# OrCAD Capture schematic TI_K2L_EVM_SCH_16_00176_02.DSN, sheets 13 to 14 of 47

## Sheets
13 PAGE36 : K2L_CLK_GEN2: size C; title: CDCM62008 Clk2, 100 / 156.25, Power Filter for Clock
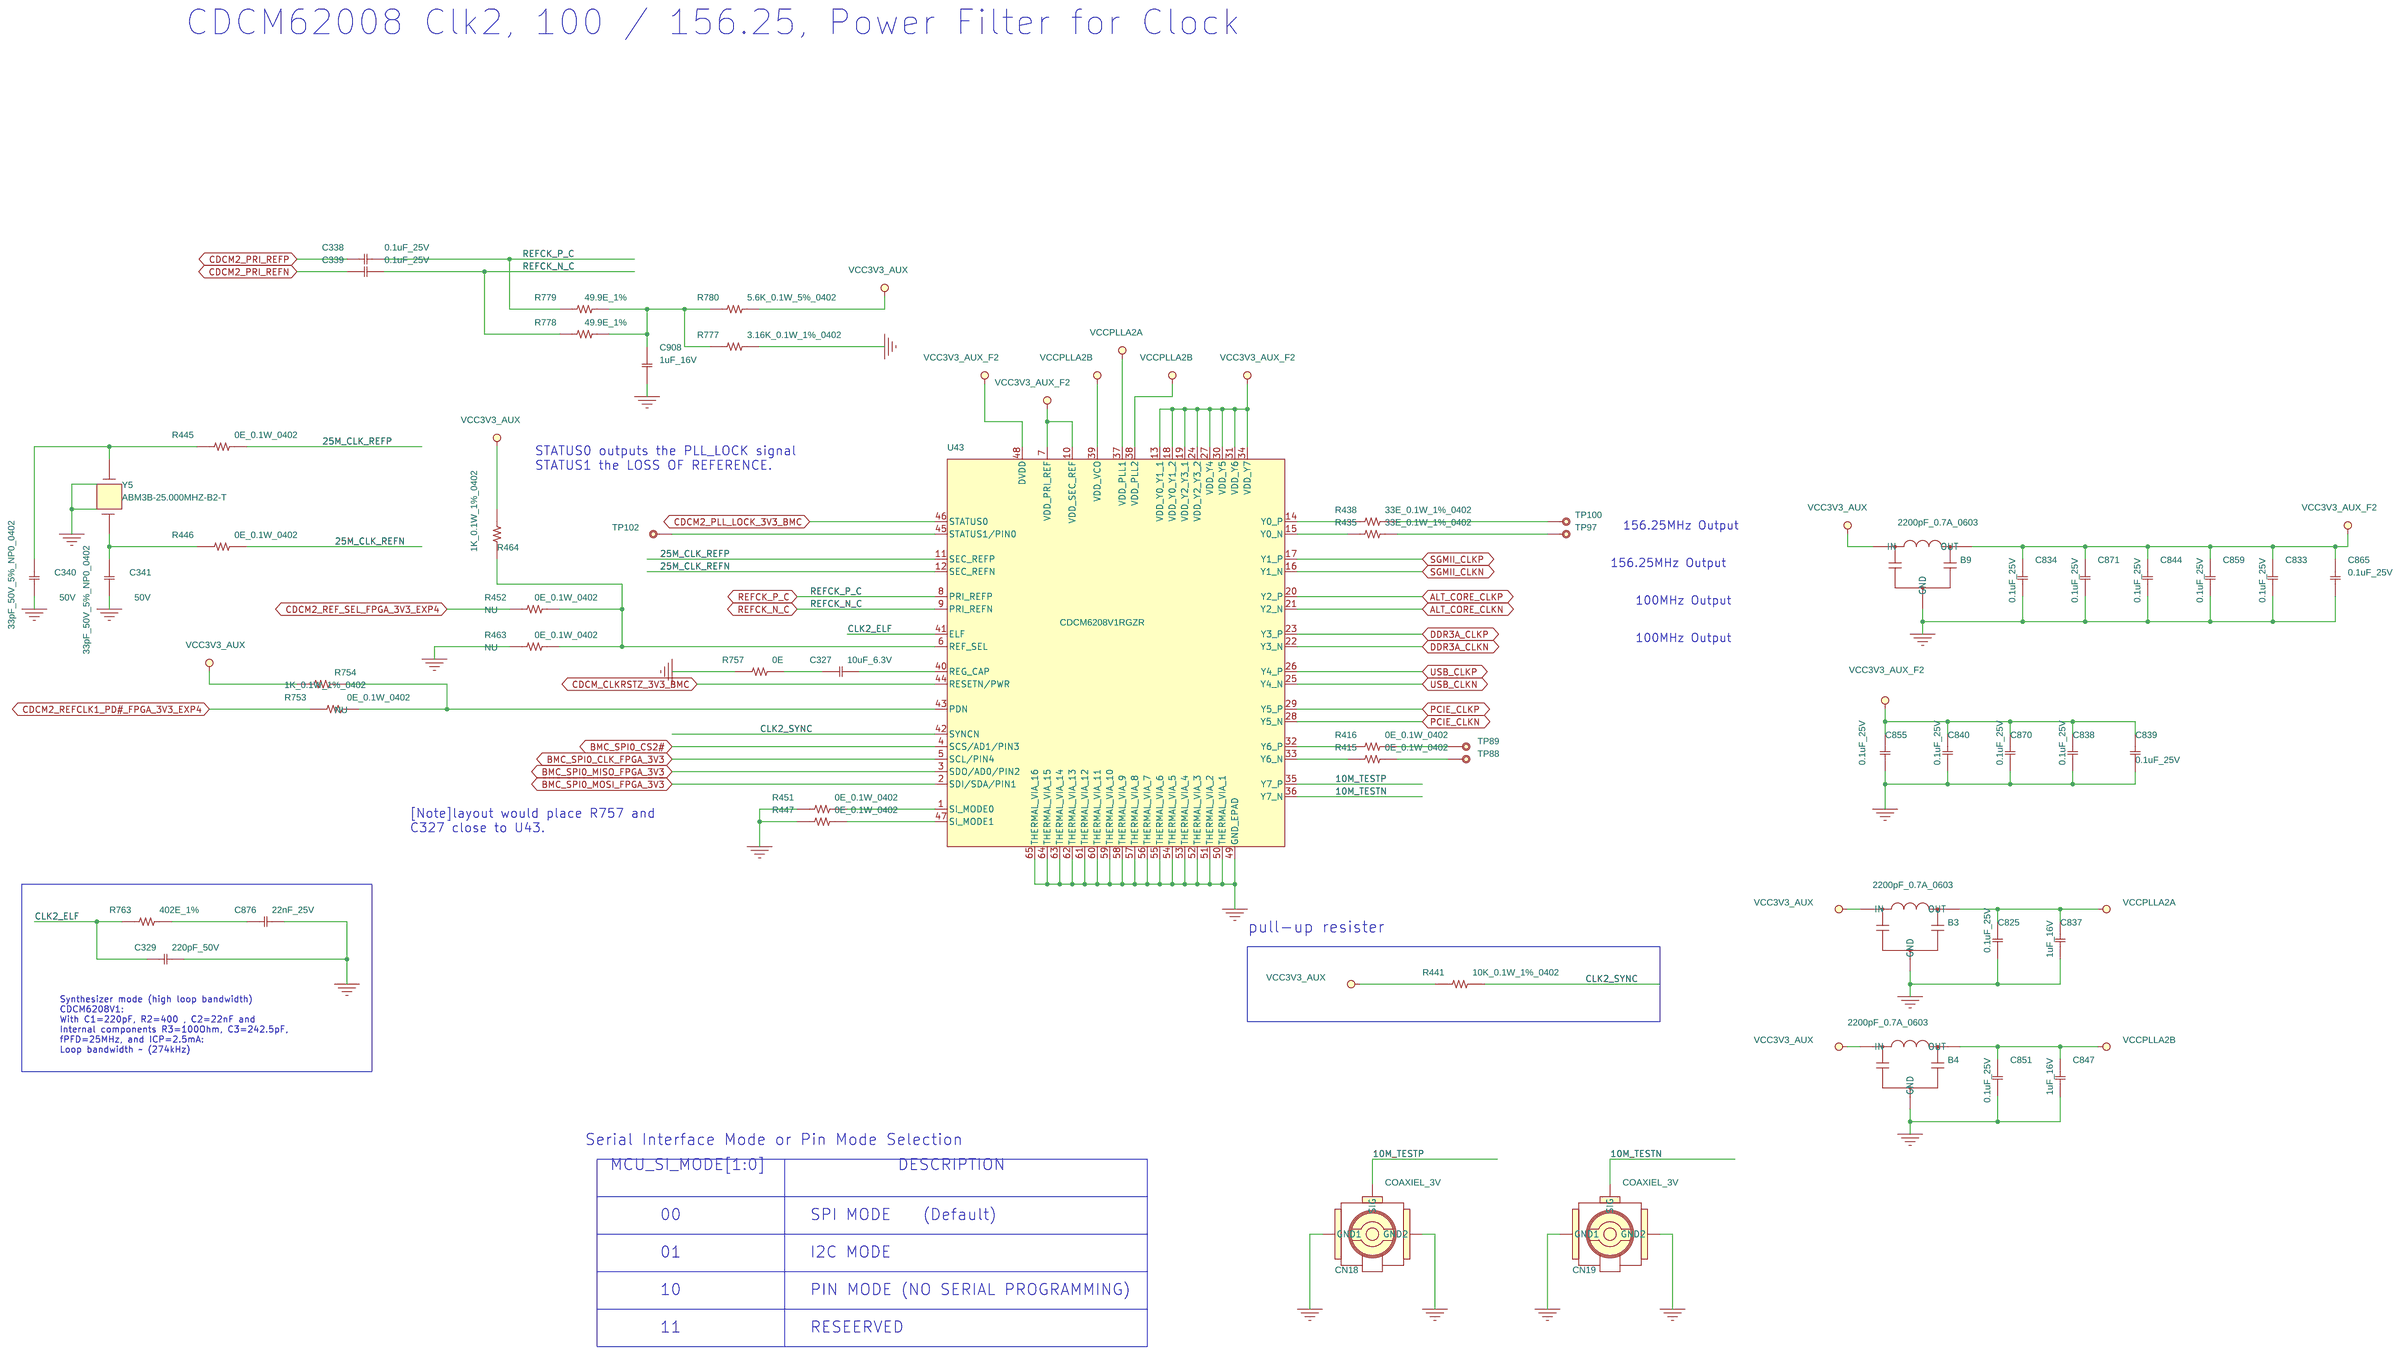
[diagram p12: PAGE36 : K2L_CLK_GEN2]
14 PAGE39 : K2L_XDS200_3: size C; title: XDS200 / debug hdr, oscillators
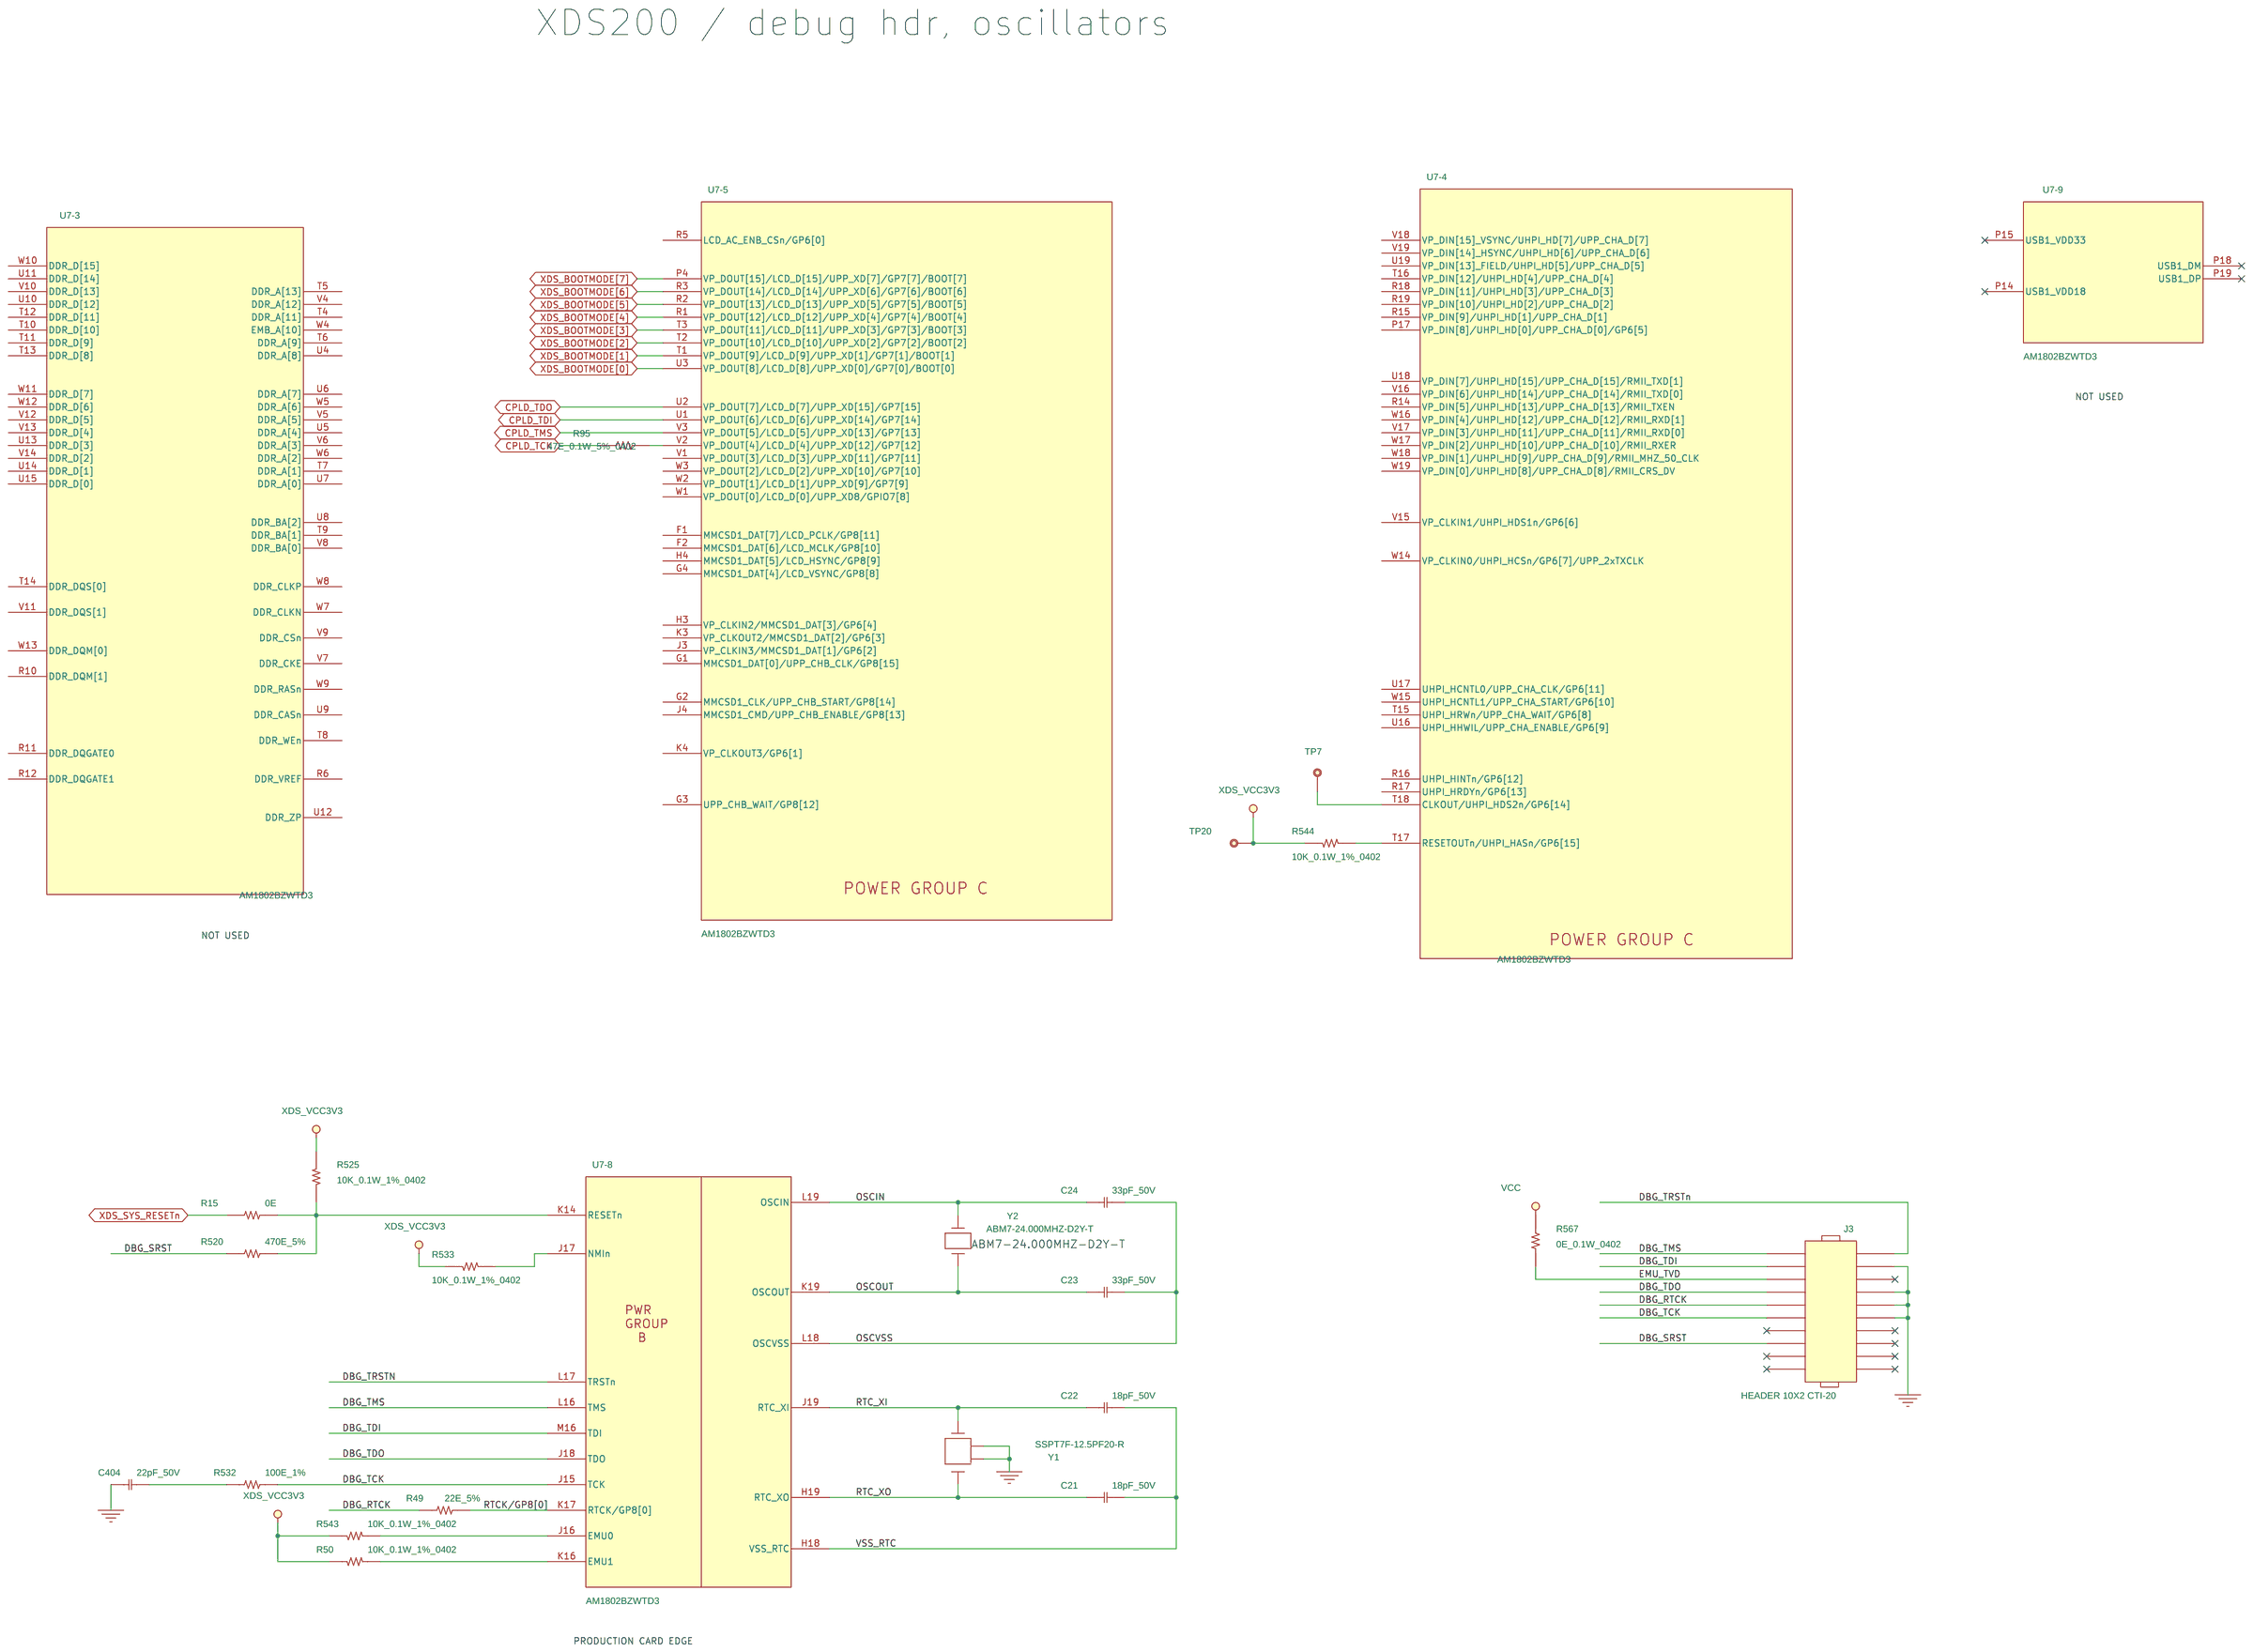
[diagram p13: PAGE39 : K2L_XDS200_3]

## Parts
sheet PAGE36 : K2L_CLK_GEN2
B3  2200pF_0.7A_0603  [L_3P_70_63X35]
B4  2200pF_0.7A_0603  [L_3P_70_63X35]
B9  2200pF_0.7A_0603  [L_3P_70_63X35]
C327  10uF_6.3V  [C0603]
C329  220pF_50V  [C0603]
C338  0.1uF_25V  [C0402]
C339  0.1uF_25V  [C0402]
C340  33pF_50V_5%_NP0_0402  [C0402]
C341  33pF_50V_5%_NP0_0402  [C0402]
C825  0.1uF_25V  [C0402]
C833  0.1uF_25V  [C0402]
C834  0.1uF_25V  [C0402]
C837  1uF_16V  [C0402]
C838  0.1uF_25V  [C0402]
C839  0.1uF_25V  [C0402]
C840  0.1uF_25V  [C0402]
C844  0.1uF_25V  [C0402]
C847  1uF_16V  [C0402]
C851  0.1uF_25V  [C0402]
C855  0.1uF_25V  [C0402]
C859  0.1uF_25V  [C0402]
C865  0.1uF_25V  [C0402]
C870  0.1uF_25V  [C0402]
C871  0.1uF_25V  [C0402]
C876  22nF_25V  [C0402]
C908  1uF_16V  [C0402]
CN18  COAXIEL_3V  [HS_UFL-R-SMT-1]
CN19  COAXIEL_3V  [HS_UFL-R-SMT-1]
R415  0E_0.1W_0402  [R0402]
R416  0E_0.1W_0402  [R0402]
R435  33E_0.1W_1%_0402  [R0402]
R438  33E_0.1W_1%_0402  [R0402]
R441  10K_0.1W_1%_0402  [R0402]
R445  0E_0.1W_0402  [R0402]
R446  0E_0.1W_0402  [R0402]
R447  0E_0.1W_0402  [R0402]
R451  0E_0.1W_0402  [R0402]
R452  0E_0.1W_0402  [R0402]
R463  0E_0.1W_0402  [R0402]
R464  1K_0.1W_1%_0402  [R0402]
R753  0E_0.1W_0402  [R0402]
R754  1K_0.1W_1%_0402  [R0402]
R757  0E  [R0402]
R763  402E_1%  [R0603]
R777  3.16K_0.1W_1%_0402  [R0402]
R778  49.9E_1%  [R0402]
R779  49.9E_1%  [R0402]
R780  5.6K_0.1W_5%_0402  [R0402]
TP88  TP  [TP-S40]
TP89  TP  [TP-S40]
TP97  TP  [TP-S40]
TP100  TP  [TP-S40]
TP102  TP  [TP-S40]
U43  CDCM6208V1RGZR  [QFN_48P_20_276X276_TP161V16]
Y5  ABM3B-25.000MHZ-B2-T  [XTAL_ABM3B]
sheet PAGE39 : K2L_XDS200_3
C21  18pF_50V  [C0402]
C22  18pF_50V  [C0402]
C23  33pF_50V  [C0402]
C24  33pF_50V  [C0402]
C404  22pF_50V  [C0402]
J3  HEADER 10X2 CTI-20  [SAMFTR-110-03-G-D-LC]
R15  0E  [R0402]
R49  22E_5%  [R0402]
R50  10K_0.1W_1%_0402  [R0402]
R95  47E_0.1W_5%_0402  [R0402]
R520  470E_5%  [R0402]
R525  10K_0.1W_1%_0402  [R0402]
R532  100E_1%  [R0402]
R533  10K_0.1W_1%_0402  [R0402]
R543  10K_0.1W_1%_0402  [R0402]
R544  10K_0.1W_1%_0402  [R0402]
R567  0E_0.1W_0402  [R0402]
TP7  TP  [TP-S40]
TP20  TP  [TP-S40]
U7  AM1802BZWTD3  [BGA80P_16X16_361]  (sections -1,-10,-11,-12,-13,-14,-15,-16,-2,-3,-4,-5,-6,-7,-8,-9)
Y1  SSPT7F-12.5PF20-R  [XTAL_SSPT7F]
Y2  ABM7-24.000MHZ-D2Y-T  [XTAL_ABM7_1]

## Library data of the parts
B3 B4 B9 = 1212_FILTER_NFW31SP106X1E4L_0: EMI Filter 0.7A SMD 3P NFM18CC222R1C3; Characteristic: 0.7A; Distributor_name: DIGIKEY; Distributor_part_number: 490-6965-1-ND; EIC Part#: 04_00026_01; Manufacture: Murata; Manufacture Part Number: NFM18CC222R1C3D; Manufacture(English): Murata; Manufacture_Part_Number: NFM18CC222R1C3D; Manufacturer: Murata; Manufacturer_Part_No: NFM18CC222R1C3D; Mfg: Murata Electronics North America; Mfg Part#: 04_00026_01; Mfr_name: Murata; Mfr_part_number: NFM18CC222R1C3D; Package: 0603; Part_Number: 1212002287; Price @ 1: 0.28000; Price @ 10K: 0.09855; Price @ 1K: 0.11242; ProcessType: SMT; Tolerance: 20%; Vendor: DIGIKEY; Vendor_Part_No: 490-6965-1-ND; eI Part#: 04_00026_01
C327 = 11_C_0: CAP CER 10UF 6.3V 20% X5R 0603; Avalue_Part_Number: E1121610610H; Characteristic: 6.3V; Distributor_name: DIGIKEY; Distributor_part_number: 587-3383-1-ND; EIC Part#: 03_00605_01; Manufacture: Taiyo Yuden; Manufacture Part Number: JMK107ABJ106MAHT; Manufacture(English): Taiyo Yuden; Manufacture_Part_Number: JMK107ABJ106MAHT; Manufacturer: Taiyo Yuden; Manufacturer_Part_No: JMK107ABJ106MAHT; Mfg: Taiyo Yuden; Mfg Part#: JMK107ABJ106MAHT; Mfr_name: Taiyo Yuden; Mfr_part_number: JMK107ABJ106MAHT; Package: 0603; Part_Number: 1100004184; Price @ 1: 0.32000; Price @ 10K: 0.06105; Price @ 1K: 0.07755; ProcessType: SMT; Tolerance: 20%; Vendor: DIGIKEY; Vendor Part#: 587-3383-1-ND; Vendor_Part_No: 587-3383-1-ND; eI Part#: 03_00605_01
C329 = 11_C_0: CAP CER 220PF 50V 10% X7R 0603; Distributor_name: DIGIKEY; Distributor_part_number: 490-1483-1-ND; EIC Part#: 03_00601_01; Manufacture: Murata; Manufacture Part Number: GRM188R71H221KA01D; Manufacture(English): Murata; Manufacture_Part_Number: GRM188R71H221KA01D; Manufacturer: Murata; Manufacturer_Part_No: GRM188R71H221KA01D; Mfg: Murata Electronics North America; Mfg Part#: 03_00601_01; Mfr_name: Murata; Mfr_part_number: GRM188R71H221KA01D; Oper. Temp. Range: -55C to 85C; Package: 0603; Price @ 1: 0.10000; Price @ 10K: 0.00897; Price @ 1K: 0.01170; ProcessType: SMT; RoHS: Yes; Tolerance: 10%; Vendor: DIGIKEY; Vendor Part#: 490-1483-1-ND; Vendor_Part_No: 490-1483-1-ND; Voltage: 50V; eI Part#: 03_00601_01
C338 C339 C825 C833 C834 C838-C840 C844 C851 C855 C859 C865 C870 C871 = 11_C_0: CAP CER 0.1UF 25V 10% X5R 0402; Avalue_Part_Number: E1123510400H; Distributor_name: DIGIKEY; Distributor_part_number: 445-4964-1-ND; EIC Part#: 03_00470_02; MOUNTED: <MOUNTED>; Manufacture: TDK Corporation; Manufacture Part Number: C1005X5R1E104K050BC; Manufacture(English): TDK Corporation; Manufacture_Part_Number: GRM155R71C104KA88D; Manufacturer: TDK Corporation; Manufacturer_Part_No: C1005X5R1E104K050BC; Mfg: Murata Electronics North America; Mfg Part#: 03_00470_02; Mfr_name: TDK Corporation; Mfr_part_number: C1005X5R1E104K050BC; Package: 0402; Price @ 1: 0.10000; Price @ 1K: 0.00420; ProcessType: SMT; Tolerance: 10%; Vendor: DIGIKEY; Vendor Part#: 445-4964-1-ND; Vendor_Part_No: 445-4964-1-ND; eI Part#: 03_00470_02
C340 C341 = 11_C_12: CAP CER 33PF 50V 5% NPO 0402; Characteristic: <Characteristic>; Distributor_name: DIGIKEY; Distributor_part_number: 311-1020-1-ND; EIC Part#: 03_00019_01; Manufacture: Yageo; Manufacture Part Number: CC0402JRNPO9BN330; Manufacture(English): Yageo; Manufacture_Part_Number: CC0402JRNPO9BN330; Manufacturer: Yageo; Manufacturer_Part_No: CC0402JRNPO9BN330; Mfg: Yageo; Mfg Part#: 03_00019_01; Mfr_name: Yageo; Mfr_part_number: CC0402JRNPO9BN330; Oper. Temp. Range: -55C to 85C; Package: 0402; Price @ 1: 0.10000; Price @ 10K: 0.00227; Price @ 1K: 0.00324; ProcessType: SMT; RoHS: Yes; Tolerance: 10%; Vendor: DIGIKEY; Vendor Part#: 311-1020-1-ND; Vendor_Part_No: 311-1020-1-ND; Voltage: 50V; eI Part#: 03_00019_01
C837 C847 C908 = 11_C_0: CAP CER 1UF 16V 10% X5R 0402; Characteristic: 6.3V; Distributor_name: DIGIKEY; Distributor_part_number: 445-4978-1-ND; EIC Part#: 03_00355_04; Manufacture: TDK Corporation; Manufacture Part Number: C1005X5R1C105K050BC; Manufacture(English): TDK Corporation; Manufacture_Part_Number: C1005X5R1C105K050BC; Manufacturer: TDK Corporation; Manufacturer_Part_No: C1005X5R1C105K050BC; Mfg: TDK Corporation; Mfg Part#: C1005X5R1C105K050BC; Mfr_name: TDK Corporation; Mfr_part_number: C1005X5R1C105K050BC; Package: 0402; Part_Number: 1100000870; Price @ 1: 0.10000; Price @ 10K: 0.01155; Price @ 1K: 0.01650; ProcessType: SMT; Tolerance: 10%; Vendor: DIGIKEY; Vendor_Part_No: 445-4978-1-ND; eI Part#: 03_00355_04
C876 = 11_C_0: CAP CER 0.022UF 25V 10% X7R 0402; Characteristic: 25V; Distributor_name: DIGIKEY; Distributor_part_number: 445-1261-1-ND; EIC Part#: 03_00565_02; Manufacture: TDK Corporation; Manufacture Part Number: C1005X7R1E223K050BB; Manufacture(English): TDK Corporation; Manufacture_Part_Number: C1005X7R1E223K050BB; Manufacturer: TDK Corporation; Manufacturer_Part_No: C1005X7R1E223K050BB; Mfg: TDK Corporation; Mfg Part#: TBD; Mfr_name: TDK Corporation; Mfr_part_number: C1005X7R1E223K050BB; Package: 0402; Price @ 1: 0.10000; Price @ 10K: 0.00759; Price @ 1K: 0.00990; ProcessType: SMT; RoHS: Yes; Tolerance: 10%; Vendor: DIGIKEY; Vendor Part#: 445-1261-1-ND; Vendor_Part_No: 445-1261-1-ND; Voltage: 25V; eI Part#: 03_00565_02
CN18 CN19 = 1654_HS_UFL-R-SMT-1_0: CONN UMC JACK STR 50 OHM SMD; Advansus_Part_Number: 12GA1654002618; Distributor_name: DIGIKEY; Distributor_part_number: H11891CT-ND; EIC Part#: TBD; Manufacture: Hirose Electric Co Ltd; Manufacture Part Number: U.FL-R-SMT-1(10); Manufacture(English): Hirose Electric Co Ltd; Manufacture_Part_Number: U.FL-R-SMT-1(10); Manufacturer: Hirose Electric Co Ltd; Manufacturer_Part_No: U.FL-R-SMT-1(10); Mfg: Hirose Electric Co Ltd; Mfg Part#: TBD; Mfr_name: Hirose Electric Co Ltd; Mfr_part_number: U.FL-R-SMT-1(10); Package: COAXIEL3P; Part_Number: 1654002618; Price @ 1: 1.67000; Price @ 10K: 0.58000; Price @ 1K: 0.70400; ProcessType: SMT; Vendor: DIGIKEY; Vendor_Part_No: H11891CT-ND; eI Part#: TBD
R415 R416 R447 R451 = 10_R_0: RES 0.0 OHM 1/10W JUMP 0402 SMD; Characteristic: 5%; Distributor_name: DIGIKEY; Distributor_part_number: P0.0JCT-ND; EIC Part#: 02_00019_01; Manufacture: Panasonic - ECG; Manufacture Part Number: ERJ-2GE0R00X; Manufacture(English): Panasonic - ECG; Manufacture_Part_Number: ERJ-2GE0R00X; Manufacturer: Panasonic - ECG; Manufacturer_Part_No: ERJ-2GE0R00X; Mfg: Panasonic Electronic Components; Mfg Part#: 02_00019_01; Mfr_name: Panasonic - ECG; Mfr_part_number: ERJ-2GE0R00X; Package: 0402; Part_Number: 105A700004; Price @ 1: 0.05000; Price @ 10K: 0.00248; Price @ 1K: 0.00480; ProcessType: SMT; Tolerance: 5%; Vendor: DIGIKEY; Vendor_Part_No: P0.0JCT-ND; eI Part#: 02_00019_01
R435 = 10_R_0: RES 33 OHM 1/10W 1% 0402 SMD; Advansus_Part_Number: 10G212330004010; Characteristic: 5%; Distributor_name: DIGIKEY; Distributor_part_number: P33.0LCT-ND; EIC Part#: 02_00018_05; Manufacture: Panasonic - ECG; Manufacture Part Number: ERJ-2RKF33R0X; Manufacture(English): Panasonic - ECG; Manufacture_Part_Number: ERJ-2RKF33R0X; Manufacturer: Panasonic - ECG; Manufacturer_Part_No: ERJ-2RKF33R0X; Mfg: Panasonic Electronic Components; Mfg Part#: 02_00018_05; Mfr_name: Panasonic - ECG; Mfr_part_number: ERJ-2RKF33R0X; Package: 0402; Part_Number: 105A733064-02; Price @ 1: 0.10000; Price @ 10K: 0.00347; Price @ 1K: 0.00672; ProcessType: SMT; Tolerance: 5%; Vendor: DIGIKEY; Vendor_Part_No: P33.0LCT-ND; eI Part#: 02_00027_01
R438 = 10_R_0: RES 33 OHM 1/10W 1% 0402 SMD; Advansus_Part_Number: 10G212330004010; Characteristic: 5%; Distributor_name: DIGIKEY; Distributor_part_number: P33.0LCT-ND; EIC Part#: 02_00018_05; Manufacture: Panasonic - ECG; Manufacture Part Number: ERJ-2RKF33R0X; Manufacture(English): Panasonic - ECG; Manufacture_Part_Number: ERJ-2RKF33R0X; Manufacturer: Panasonic - ECG; Manufacturer_Part_No: ERJ-2RKF33R0X; Mfg: Panasonic Electronic Components; Mfg Part#: 02_00018_05; Mfr_name: Panasonic - ECG; Mfr_part_number: ERJ-2RKF33R0X; Package: 0402; Part_Number: 105A733064-02; Price @ 1: 0.10000; Price @ 10K: 0.00347; Price @ 1K: 0.00672; ProcessType: SMT; Tolerance: 5%; Vendor: DIGIKEY; Vendor_Part_No: P33.0LCT-ND; eI Part#: 02_00266_01
R441 = 10_R_0: RES 10K OHM 1/10W 1% 0402 SMD; Characteristic: 1%; Distributor_name: DIGIKEY; Distributor_part_number: P10.0KLCT-ND; EIC Part#: 02_00027_01; Manufacture: Panasonic - ECG; Manufacture Part Number: ERJ-2RKF1002X; Manufacture(English): Panasonic - ECG; Manufacture_Part_Number: ERJ-2RKF1002X; Manufacturer: Panasonic - ECG; Manufacturer_Part_No: ERJ-2RKF1002X; Mfg: PANASONIC ELECTRONIC COMPONENTS (VA); Mfg Part#: 02_00027_01; Mfr_name: Panasonic - ECG; Mfr_part_number: ERJ-2RKF1002X; Package: 0402; Part_Number: 105A50103A; Price @ 1: 0.10000; Price @ 10K: 0.00347; Price @ 1K: 0.00672; ProcessType: SMT; Tolerance: 1%; Vendor: DIGIKEY; Vendor_Part_No: P10.0KLCT-ND; eI Part#: 02_00027_01
R15 R445 R446 = 10_R_0: RES 0.0 OHM 1/10W JUMP 0402 SMD; Alt Mfg: Yageo; Distributor_name: DIGIKEY; Distributor_part_number: P0.0JCT-ND; EIC Part#: 02_00019_01; Manufacture: Panasonic - ECG; Manufacture Part Number: ERJ-2GE0R00X; Manufacture(English): Panasonic - ECG; Manufacture_Part_Number: ERJ-2GE0R00X; Manufacturer: Panasonic - ECG; Manufacturer_Part_No: ERJ-2GE0R00X; Mfg Part#: 02_00019_01; Mfr_name: Panasonic - ECG; Mfr_part_number: ERJ-2GE0R00X; Oper. Temp. Range: -55C to 125C; Package: 0402; ProcessType: SMT; Remark: Alt part is 1/16W; RoHS: Yes; Tolerance: 5%; Vendor: DIGIKEY; Vendor Part#: P0.0JCT-ND; Vendor_Part_No: P0.0JCT-ND; eI Part#: 02_00019_01
R452 R463 R753 = 10_R_0: RES 0.0 OHM 1/10W JUMP 0402 SMD; Characteristic: 5%; Distributor_name: DIGIKEY; Distributor_part_number: P0.0JCT-ND; EIC Part#: 02_00019_01; MOUNTED: NU; Manufacture: Panasonic - ECG; Manufacture Part Number: ERJ-2GE0R00X; Manufacture(English): Panasonic - ECG; Manufacture_Part_Number: ERJ-2GE0R00X; Manufacturer: Panasonic - ECG; Manufacturer_Part_No: ERJ-2GE0R00X; Mfg: Panasonic Electronic Components; Mfg Part#: 02_00019_01; Mfr_name: Panasonic - ECG; Mfr_part_number: ERJ-2GE0R00X; Mounting Status: NU; Mounting_Status: NU; Package: 0402; Part_Number: 105A700004; Price @ 1: 0.05000; Price @ 10K: 0.00248; Price @ 1K: 0.00480; ProcessType: SMT; Tolerance: 5%; Vendor: DIGIKEY; Vendor_Part_No: P0.0JCT-ND; eI Part#: 02_00019_01
R464 R754 = 10_R_0: RES 1.00K OHM 1/10W 1% 0402 SMD; Distributor_name: DIGIKEY; Distributor_part_number: P1.00KLCT-ND; EIC Part#: 02_00045_01; Manufacture: Panasonic - ECG; Manufacture Part Number: ERJ-2RKF1001X; Manufacture(English): Panasonic - ECG; Manufacture_Part_Number: ERJ-2RKF1001X; Manufacturer: Panasonic - ECG; Manufacturer_Part_No: ERJ-2RKF1001X; Mfg Part#: 02_00045_01; Mfr_name: Panasonic - ECG; Mfr_part_number: ERJ-2RKF1001X; Price @ 1: 0.10000; Price @ 10K: 0.00347; Price @ 1K: 0.00672; Vendor: DIGIKEY; Vendor_Part_No: P1.00KLCT-ND; eI Part#: 02_00045_01
R757 = 10_R_0: RES 0.0 OHM 1/10W JUMP 0402 SMD; Characteristic: 5%; Distributor_name: DIGIKEY; Distributor_part_number: P0.0JCT-ND; EIC Part#: 02_00019_01; MOUNTED: <MOUNTED>; Manufacture: Panasonic - ECG; Manufacture Part Number: ERJ-2GE0R00X; Manufacture(English): Panasonic - ECG; Manufacture_Part_Number: ERJ-2GE0R00X; Manufacturer: Panasonic - ECG; Manufacturer_Part_No: ERJ-2GE0R00X; Mfg: Panasonic Electronic Components; Mfg Part#: 02_00019_01; Mfr_name: Panasonic - ECG; Mfr_part_number: ERJ-2GE0R00X; Package: 0402; Part_Number: 105A700004; Price @ 1: 0.05000; Price @ 10K: 0.00248; Price @ 1K: 0.00480; ProcessType: SMT; Tolerance: 5%; Vendor: DIGIKEY; Vendor_Part_No: P0.0JCT-ND; eI Part#: 02_00019_01
R763 = 10_R_0: RES 402 OHM 1/10W 1% 0603 SMD; Alt Mfg: Yageo; Alt Mfg Part#: RC0402JR-070RL; Distributor_name: DIGIKEY; Distributor_part_number: P402HCT-ND; EIC Part#: 02_00968_01; Manufacture: Panasonic - ECG; Manufacture Part Number: ERJ-3EKF4020V; Manufacture(English): Panasonic - ECG; Manufacture_Part_Number: ERJ-3EKF4020V; Manufacturer: Panasonic - ECG; Manufacturer_Part_No: ERJ-3EKF4020V; Mfg Part#: 02_00968_01; Mfr_name: Panasonic - ECG; Mfr_part_number: ERJ-3EKF4020V; Oper. Temp. Range: -55C to 125C; Package: 0603; ProcessType: SMT; Remark: Alt part is 1/16W; RoHS: Yes; Tolerance: 5%; Vendor: DIGIKEY; Vendor Part#: P402HCT-ND; Vendor_Part_No: P402HCT-ND; eI Part#: 02_00045_01
R777 = 10_R_0: RES 3.16K OHM 1/10W 1% 0402 SMD; AVL_Part: AVL; Advansus_Part_Number: 10G212316114030; Avalue_Part_Number: E1050531610H; Characteristic: 1%; Distributor_name: DIGIKEY; Distributor_part_number: P3.16KLCT-ND; EIC Part#: 02_00247_01; Manufacture: Panasonic - ECG; Manufacture Part Number: ERJ-2RKF3161X; Manufacture(English): Panasonic - ECG; Manufacture_Part_Number: ERJ-2RKF3161X; Manufacturer: Panasonic - ECG; Manufacturer_Part_No: ERJ-2RKF3161X; Mfg: Panasonic Electronic Components; Mfg Part#: 02_00247_01; Mfr_name: Panasonic - ECG; Mfr_part_number: ERJ-2RKF3161X; Package: 0402; Part_Number: 1000001652-03; Price @ 1: 0.10000; Price @ 10K: 0.00347; Price @ 1K: 0.00672; ProcessType: SMT; Tolerance: 1%; Vendor: DIGIKEY; Vendor_Part_No: P3.16KLCT-ND; eI Part#: 02_00247_01
R778 R779 = 10_R_0: RES 49.9 OHM 1/10W 1% 0402 SMD; Characteristic: 1%; Distributor_name: DIGIKEY; Distributor_part_number: P49.9LCT-ND; EIC Part#: 02_00025_01; Manufacture: Panasonic - ECG; Manufacture Part Number: ERJ-2RKF49R9X; Manufacture(English): Panasonic - ECG; Manufacture_Part_Number: ERJ-2RKF49R9X; Manufacturer: Panasonic - ECG; Manufacturer_Part_No: ERJ-2RKF49R9X; Mfg: Panasonic - ECG; Mfg Part#: ERJ-2RKF49R9X; Mfr_name: Panasonic - ECG; Mfr_part_number: ERJ-2RKF49R9X; Package: 0402; Part_Number: 105A549964-03; Price @ 1: 0.10000; Price @ 10K: 0.00347; Price @ 1K: 0.00672; ProcessType: SMT; Tolerance: 1%; Vendor: DIGIKEY; Vendor Part#: P49.9LCT-ND; Vendor_Part_No: P49.9LCT-ND; eI Part#: 02_00025_01
R780 = 10_R_0: RES 5.6K OHM 1/10W 5% 0402 SMD; AVL_Part: AVL; Advansus_Part_Number: 10G212560114030; Avalue_Part_Number: E1050505620H; Distributor_name: DIGIKEY; Distributor_part_number: P5.6KJTR-ND; EIC Part#: 02_00169_01; Manufacture: Panasonic - ECG; Manufacture Part Number: ERJ-2GEJ562X; Manufacture(English): Panasonic - ECG; Manufacture_Part_Number: ERJ-2GEJ562X; Manufacturer: Panasonic - ECG; Manufacturer_Part_No: ERJ-2GEJ562X; Mfg: Panasonic Electronic Components; Mfg Part#: ERJ-2GEJ562X; Mfr_name: Panasonic - ECG; Mfr_part_number: ERJ-2GEJ562X; Package: 0402; Part_Number: 105A55601A-03; Price @ 1: 0.10000; Price @ 10K: 0.00347; Price @ 1K: 0.00672; ProcessType: SMT; Tolerance: 5%; Vendor: DIGIKEY; Vendor_Part_No: P5.6KJTR-ND; eI Part#: 02_00169_01
TP88 TP89 TP97 TP100 TP102 = 00_TP28_0: TEST PAD TP; Advansus_Part_Number: 0030000003; Avalue_Part_Number: 0030000003; Distributor_name: NA; Distributor_part_number: NA; EIC Part#: NA; Manufacture: NA; Manufacture Part Number: NA; Manufacture(English): NA; Manufacture_Part_Number: NA; Manufacturer: NA; Manufacturer_Part_No: NA; Mfg: NA; Mfg Part#: NA; Mfr_name: NA; Mfr_part_number: NA; Part_Number: 0030000003; Price @ 1: NA; Price @ 10K: NA; Price @ 1K: NA; ProcessType: SMT; Vendor: NA; Vendor_Part_No: NA; eI Part#: NA
U43 = 141_TI_CDCM6208_1: IC CLK GEN 2:8 LOW JITTER 48VQFN; AVL_Part: AVL; Distributor_name: DIGIKEY; Distributor_part_number: 296-36574-1-ND; EIC Part#: 01_01119_01; Manufacture: TI; Manufacture(English): TI; Manufacturer: TI; Mfg: TI; Mfg Part#: 01_01119_01; Mfr_name: TI; Oper. Temp. Range: -40°C ~ 85°C; Package: VQFN48; Price @ 1: 12.07000; Price @ 10K: 5.85000; Price @ 1K: 5.96700; ProcessType: SMT; RoHS: Yes; Vendor: DIGIKEY; Vendor Part#: CDCM6208V1RGZR-ND; Vendor_Part_No: 296-36574-1-ND; eI Part#: TBD
Y5 = CRYSTAL-4_PIN: CRYSTAL 25MHZ 18PF SMD; Distributor_name: DIGIKEY; Distributor_part_number: 535-9128-1-ND; EIC Part#: 08_00006_01; Manufacture: Abracon Corporation; Manufacture(English): Abracon Corporation; Manufacturer: Abracon Corporation; Mfg: Abracon Corporation; Mfg Part#: 08_00006_01; Mfr_name: Abracon Corporation; Oper. Temp. Range: -20C to 60C; Package: 5.0mm x 3.2mm; Price @ 1: 1.43000; Price @ 10K: 0.53200; Price @ 1K: 0.53200; RoHS: Yes; Specifications: CRYSTAL 25.000MHZ 18PF FUND SMD; Vendor: DIGIKEY; Vendor Part#: 535-9128-1-ND; Vendor_Part_No: 535-9128-1-ND; eI Part#: 08_00006_01
C21 C22 = 11_C_12: CAP CER 18PF 50V 5% NP0 0402; Characteristic: <Characteristic>; Distributor_name: DIGIKEY; Distributor_part_number: 490-5858-1-ND; EIC Part#: 03_00076_02; Manufacture: Murata; Manufacture Part Number: GRM1885C1H180JA01D; Manufacture(English): Murata; Manufacture_Part_Number: GRM1555C1H180JA01D; Manufacturer: Murata; Manufacturer_Part_No: GRM1555C1H180JA01D; Mfg Part#: GRM1555C1H180JA01D; Mfr_name: Murata; Mfr_part_number: GRM1555C1H180JA01D; Oper. Temp. Range: -55C to 85C; Package: 0402; ProcessType: SMT; RoHS: Yes; Vendor: DIGIKEY; Vendor Part#: 490-5858-1-ND; Vendor_Part_No: 490-5858-1-ND; eI Part#: 03_00076_02
C23 C24 = 11_C_12: CAP CER 33PF 50V 5% NPO 0402; Characteristic: <Characteristic>; Distributor_name: DIGIKEY; Distributor_part_number: 311-1020-1-ND; EIC Part#: 03_00019_01; Manufacture: Yageo; Manufacture Part Number: CC0402JRNPO9BN330; Manufacture(English): Yageo; Manufacture_Part_Number: CC0402JRNPO9BN330; Manufacturer: Yageo; Manufacturer_Part_No: CC0402JRNPO9BN330; Mfg: Yageo; Mfg Part#: 03_00019_01; Mfr_name: Yageo; Mfr_part_number: CC0402JRNPO9BN330; Oper. Temp. Range: -55C to 85C; Package: 0402; Price @ 1: 0.10000; Price @ 10K: 0.00227; Price @ 1K: 0.00324; ProcessType: SMT; RoHS: Yes; Vendor: DIGIKEY; Vendor Part#: 311-1020-1-ND; Vendor_Part_No: 311-1020-1-ND; eI Part#: 03_00019_01
C404 = 11_C_0: CAP CER 22PF 50V 0402 SMD; Alt Mfg: Yageo; Alt Mfg Part#: CC0402JRNPO9BN220; Alternate_Mfr: TDK Corporation; Alternate_Partno: C1005C0G1H220J050BA; Distributor_name: DIGIKEY; Distributor_part_number: PCC220CQCT-ND; EIC Part#: 03_00204_02; Manufacture: Panasonic - ECG; Manufacture Part Number: ECJ-0EC1H220J; Manufacture(English): Panasonic - ECG; Manufacture_Part_Number: ECJ-0EC1H220J; Manufacturer: Panasonic - ECG; Manufacturer_Part_No: ECJ-0EC1H220J; Mfg: Panasonic - ECG; Mfg Part#: 03_00204_02; Mfr_name: Panasonic - ECG; Mfr_part_number: ECJ-0EC1H220J; Oper. Temp. Range: -55C to 125C; Package: 0402; Price @ 1: TBD; Price @ 10K: TBD; Price @ 1K: TBD; ProcessType: SMT; RoHS: Yes; Tolerance: 5%; Vendor: DIGIKEY; Vendor Part#: PCC220CQCT-ND; Vendor_Part_No: PCC220CQCT-ND; eI Part#: 03_00204_02
J3 = HEADER_10X2_0: CONN HEADER 20POS 1.27MM DUL SMD; Distributor_name: TBD; Distributor_part_number: TBD; EIC Part#: 09_00198_01; Manufacture: Samtec Inc; Manufacture Part Number: FTR-110-03-G-D-LC-06; Manufacture(English): Samtec Inc; Manufacture_Part_Number: FTR-110-03-G-D-LC-06; Manufacturer: Samtec Inc; Manufacturer_Part_No: FTR-110-03-G-D-LC-06; Mfg: Samtec Inc; Mfg Part#: 09_00198_01; Mfr_name: Samtec Inc; Mfr_part_number: FTR-110-03-G-D-LC-06; Vendor: TBD; Vendor Part#: FTR-110-03-G-D-LC-06-ND; Vendor_Part_No: TBD; eI Part#: 09_00198_01
R49 = 10_R_0: RES 22 OHM 1/16W 1% 0402 SMD; Characteristic: 5%; Distributor_name: DIGIKEY; Distributor_part_number: P22JCT-ND; EIC Part#: 02_00233_01; Manufacture: Panasonic - ECG; Manufacture Part Number: ERJ-2GEJ220X; Manufacture(English): Panasonic - ECG; Manufacture_Part_Number: ERJ-2GEJ220X; Manufacturer: Panasonic - ECG; Manufacturer_Part_No: ERJ-2GEJ220X; Mfg: Panasonic - ECG; Mfg Part#: ERJ-2GEJ220X; Mfr_name: Panasonic - ECG; Mfr_part_number: ERJ-2GEJ220X; Oper. Temp. Range: -55C to 125C; Package: 0402; ProcessType: SMT; RoHS: Yes; Tolerance: 5%; Vendor: DIGIKEY; Vendor Part#: P22JCT-ND; Vendor_Part_No: P22JCT-ND; eI Part#: 02_00233_01
R50 R525 R533 R543 R544 = 10_R_0: RES 10K OHM 1/10W 1% 0402 SMD; Alt Mfg: Yageo; Alt Mfg Part#: RC0402FR-0710KL; Distributor_name: DIGIKEY; Distributor_part_number: P10.0KLCT-ND; EIC Part#: 02_00027_01; Manufacture: Panasonic - ECG; Manufacture Part Number: ERJ-2RKF1002X; Manufacture(English): Panasonic - ECG; Manufacture_Part_Number: ERJ-2RKF1002X; Manufacturer: Panasonic - ECG; Manufacturer_Part_No: ERJ-2RKF1002X; Mfg Part#: 02_00027_01; Mfr_name: Panasonic - ECG; Mfr_part_number: ERJ-2RKF1002X; Oper. Temp. Range: -55C ~ 125C; Package: 0402; Price @ 1: 0.10000; Price @ 10K: 0.00347; Price @ 1K: 0.00672; ProcessType: SMT; Remark: Alt part is 1/16W; RoHS: Yes; Tolerance: 1%; Vendor: DIGIKEY; Vendor Part#: P10.0KLCT-ND; Vendor_Part_No: P10.0KLCT-ND; eI Part#: 02_00027_01
R95 = 10_R_0: RES 47 OHM 1/10W 5% 0402 SMD; Alt Mfg: Yageo; Alt Mfg Part#: RC0402JR-070RL; Distributor_name: DIGIKEY; Distributor_part_number: P47JCT-ND; EIC Part#: 02_00558_01; Manufacture: Panasonic - ECG; Manufacture Part Number: ERJ-2GEJ470X; Manufacture(English): Panasonic - ECG; Manufacture_Part_Number: ERJ-2GEJ470X; Manufacturer: Panasonic - ECG; Manufacturer_Part_No: ERJ-2GEJ470X; Mfg Part#: 02_00558_01; Mfr_name: Panasonic - ECG; Mfr_part_number: ERJ-2GEJ470X; Oper. Temp. Range: -55C to 125C; Package: 0402; ProcessType: SMT; Remark: Alt part is 1/16W; RoHS: Yes; Tolerance: 5%; Vendor: DIGIKEY; Vendor Part#: P47JCT-ND; Vendor_Part_No: P47JCT-ND; eI Part#: 02_00558_01
R520 = 10_R_0: RES 470 OHM 1/10W 5% 0402 SMD; Alt Mfg: Yageo; Alt Mfg Part#: RC0402JR-070RL; Distributor_name: DIGIKEY; Distributor_part_number: P470JCT-ND; EIC Part#: 02_00483_01; Manufacture: Panasonic - ECG; Manufacture Part Number: ERJ-2GEJ471X; Manufacture(English): Panasonic - ECG; Manufacture_Part_Number: ERJ-2GEJ471X; Manufacturer: Panasonic - ECG; Manufacturer_Part_No: ERJ-2GEJ471X; Mfg Part#: 02_00483_01; Mfr_name: Panasonic - ECG; Mfr_part_number: ERJ-2GEJ471X; Oper. Temp. Range: -55C to 125C; Package: 0402; ProcessType: SMT; Remark: Alt part is 1/16W; RoHS: Yes; Tolerance: 5%; Vendor: DIGIKEY; Vendor Part#: P470JDKR-ND; Vendor_Part_No: P470JCT-ND; eI Part#: 02_00558_01
R532 = 10_R_0: RES 100 OHM 1/10W 1% 0402 SMD; Distributor_name: DIGIKEY; Distributor_part_number: P100LCT-ND; EIC Part#: 02_00043_02; Manufacture: Panasonic - ECG; Manufacture Part Number: ERJ-2RKF1000X; Manufacture(English): Panasonic - ECG; Manufacture_Part_Number: ERJ-2RKF1000X; Manufacturer: Panasonic - ECG; Manufacturer_Part_No: ERJ-2RKF1000X; Mfg Part#: 02_00043_02; Mfr_name: Panasonic - ECG; Mfr_part_number: ERJ-2RKF1000X; Oper. Temp. Range: -55C to 125C; Package: 0402; ProcessType: SMT; RoHS: Yes; Tolerance: 1%; Vendor: DIGIKEY; Vendor Part#: P100LCT-ND; Vendor_Part_No: P100LCT-ND; eI Part#: 02_00558_01
R567 = 10_R_0: RES 0.0 OHM 1/10W JUMP 0402 SMD; Alt Mfg: Yageo; Distributor_name: DIGIKEY; Distributor_part_number: P0.0JCT-ND; EIC Part#: 02_00019_01; Manufacture: Panasonic - ECG; Manufacture Part Number: ERJ-2GE0R00X; Manufacture(English): Panasonic - ECG; Manufacture_Part_Number: ERJ-2GE0R00X; Manufacturer: Panasonic - ECG; Manufacturer_Part_No: ERJ-2GE0R00X; Mfg: Panasonic - ECG; Mfg Part#: 02_00019_01; Mfr_name: Panasonic - ECG; Mfr_part_number: ERJ-2GE0R00X; Oper. Temp. Range: -55C to 125C; Package: 0402; ProcessType: SMT; Remark: Alt part is 1/16W; RoHS: Yes; Tolerance: 5%; Vendor: DIGIKEY; Vendor Part#: P0.0JCT-ND; Vendor_Part_No: P0.0JCT-ND; eI Part#: 02_00019_01
TP7 TP20 = 00_TP-S40_0: TEST PAD TP; Distributor_name: NA; Distributor_part_number: NA; EIC Part#: NA; Manufacture: NA; Manufacture Part Number: NA; Manufacture(English): NA; Manufacture_Part_Number: NA; Manufacturer: NA; Manufacturer_Part_No: NA; Mfg: NA; Mfg Part#: NA; Mfr_name: NA; Mfr_part_number: NA; Oper. Temp. Range: --NA--; Package: --NA--; Price @ 1: NA; Price @ 10K: NA; Price @ 1K: NA; ProcessType: SMT; RoHS: Yes; Vendor: NA; Vendor Part#: --NA--; Vendor_Part_No: NA; eI Part#: NA
U7 = OMAP-L138_new_5: IC ARM9 CORTEX MPU 361NFBGA; Distributor_name: DIGIKEY; Distributor_part_number: AM1802BZWTD3-ND; EIC Part#: 01_01135_01; Manufacture: TI; Manufacture(English): TI; Manufacturer: TI; Mfg: TI; Mfg Part#: 01_01135_01; Mfr_name: TI; Part #: 103922-0001R; Price @ 1: 14.51000; Price @ 1K: 14.51000; Vendor: DIGIKEY; Vendor_Part_No: AM1802BZWTD3-ND; eI Part#: 01_01147_01
Y1 = CRYSTAL_0_v2: CRYSTAL 32.768KHZ 12.5PF SMD; Alternate_Mfr: ECS Inc; Alternate_Partno: ECS-.327-12.5-38; Distributor_name: DIGIKEY; Distributor_part_number: 728-1064-1-ND; EIC Part#: 08_00137_01; Manufacture: Seiko Instruments; Manufacture(English): Seiko Instruments; Manufacturer: Seiko Instruments; Mfg: Seiko Instruments; Mfg Part#: 08_00137_01; Mfr_name: Seiko Instruments; Oper. Temp. Range: -40°C ~ 85°C; Package: 4-SMD; Part #: 102883-0032R; Price @ 1: 0.82000; Price @ 10K: 0.43500; Price @ 1K: 0.47100; RoHS: Yes; Vendor: DIGIKEY; Vendor Part#: 728-1064-1-ND; Vendor_Part_No: 728-1064-1-ND; eI Part#: 08_00137_01
Y2 = CRYSTAL_0: CRYSTAL 24MHZ 18PF SMD; Distributor_name: DIGIKEY; Distributor_part_number: 535-9845-1-ND; EIC Part#: 08_00090_01; Manufacture: Abracon Corporation; Manufacture(English): Abracon Corporation; Manufacturer: Abracon Corporation; Mfg: Abracon Corporation; Mfg Part#: 08_00090_01; Mfr_name: Abracon Corporation; Oper. Temp. Range: -40°C ~ 85°C; Package: 2-SMD; Price @ 1: 1.31000; Price @ 10K: 0.49000; Price @ 1K: 0.49000; ProcessType: SMT; RoHS: Yes; Tolerance: 20%; Vendor: DIGIKEY; Vendor Part#: 535-9845-1-ND; Vendor_Part_No: 535-9845-1-ND; eI Part#: 08_00090_01

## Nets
GND: B3.2(GND) B4.2(GND) B9.2(GND) C329.2 C340.1 C341.1 C404.2 C825.1 C833.1 C834.1 C837.2 C838.1 C839.1 C840.1 C844.1 C847.2 C851.1 C855.1 C859.1 C865.1 C870.1 C871.1 C876.2 C908.2 CN18.1(GND1) CN18.3(GND2) CN19.1(GND1) CN19.3(GND2) J3.4 J3.8 J3.10 J3.12 R447.2 R451.2 R463.2 R757.2 R777.2 U43.49(GND_EPAD) U43.50(THERMAL_VIA_1) U43.51(THERMAL_VIA_2) U43.52(THERMAL_VIA_3) U43.53(THERMAL_VIA_4) U43.54(THERMAL_VIA_5) U43.55(THERMAL_VIA_6) U43.56(THERMAL_VIA_7) U43.57(THERMAL_VIA_8) U43.58(THERMAL_VIA_9) U43.59(THERMAL_VIA_10) U43.60(THERMAL_VIA_11) U43.61(THERMAL_VIA_12) U43.62(THERMAL_VIA_13) U43.63(THERMAL_VIA_14) U43.64(THERMAL_VIA_15) U43.65(THERMAL_VIA_16) Y1.2 Y1.3 Y5.2 Y5.4 ; also on sheet 1 2 3 4 5 6 8 10 11 12 15 16 17 18 19 20 21 22 24 25 26 27 28 29 33 34 35 36 37 40 41 42 43 45 46 47
VCC3V3_AUX: B3.1(IN) B4.1(IN) B9.1(IN) R441.1 R464.1 R754.1 R780.1 ; also on sheet 2 4 6 8 11 12 16 18 19 22 25 26 27 28 29 33 35 37 40 45 47
VCC3V3_AUX_F2: B9.3(OUT) C833.2 C834.2 C838.2 C839.2 C840.2 C844.2 C855.2 C859.2 C865.2 C870.2 C871.2 U43.7(VDD_PRI_REF) U43.10(VDD_SEC_REF) U43.13(VDD_Y0_Y1_1) U43.18(VDD_Y0_Y1_2) U43.19(VDD_Y2_Y3_1) U43.24(VDD_Y2_Y3_2) U43.27(VDD_Y4) U43.30(VDD_Y5) U43.31(VDD_Y6) U43.34(VDD_Y7) U43.48(DVDD)
VCCPLLA2A: B3.3(OUT) C825.2 C837.1 U43.37(VDD_PLL1)
VCCPLLA2B: B4.3(OUT) C847.1 C851.2 U43.38(VDD_PLL2) U43.39(VDD_VCO)
VSS_RTC: C21.1 C22.1 U7.H18(VSS_RTC)
10M_TESTN: CN19.2(SIG) U43.36(Y7_N)
10M_TESTP: CN18.2(SIG) U43.35(Y7_P)
25M_CLK_REFN: R446.2 U43.12(SEC_REFN)
25M_CLK_REFP: R445.2 U43.11(SEC_REFP)
ALT_CORE_CLKN: U43.21(Y2_N) ; also on sheet 16
ALT_CORE_CLKP: U43.20(Y2_P) ; also on sheet 16
BMC_SPI0_CLK_FPGA_3V3: U43.5(SCL/PIN4) ; also on sheet 5 11 27
BMC_SPI0_CS2#: U43.4(SCS/AD1/PIN3) ; also on sheet 5
BMC_SPI0_MISO_FPGA_3V3: U43.3(SDO/AD0/PIN2) ; also on sheet 5 11 27
BMC_SPI0_MOSI_FPGA_3V3: U43.2(SDI/SDA/PIN1) ; also on sheet 5 11 27
CDCM2_PLL_LOCK_3V3_BMC: U43.46(STATUS0) ; also on sheet 5
CDCM2_PRI_REFN: C339.1 ; also on sheet 16
CDCM2_PRI_REFP: C338.1 ; also on sheet 16
CDCM2_REF_SEL_FPGA_3V3_EXP4: R452.2 ; also on sheet 27
CDCM2_REFCLK1_PD#_FPGA_3V3_EXP4: R753.2 ; also on sheet 27
CDCM_CLKRSTZ_3V3_BMC: U43.44(RESETN/PWR) ; also on sheet 5 11
CLK2_ELF: C329.1 R763.1 U43.41(ELF)
CLK2_SYNC: R441.2 U43.42(SYNCN)
CPLD_TCK: R95.1 ; also on sheet 42
CPLD_TDI: U7.U1(VP_DOUT[6]/LCD_D[6]/UPP_XD[14]/GP7[14]) ; also on sheet 42
CPLD_TDO: U7.U2(VP_DOUT[7]/LCD_D[7]/UPP_XD[15]/GP7[15]) ; also on sheet 42
CPLD_TMS: U7.V3(VP_DOUT[5]/LCD_D[5]/UPP_XD[13]/GP7[13]) ; also on sheet 42
DBG_RTCK: J3.9 R49.2
DBG_SRST: J3.15 R520.1
DBG_TCK: J3.11 R532.2 U7.J15(TCK)
DBG_TDI: J3.3 U7.M16(TDI)
DBG_TDO: J3.7 U7.J18(TDO)
DBG_TMS: J3.1 U7.L16(TMS)
DBG_TRSTN: J3.2 U7.L17(TRSTn)
DDR3A_CLKN: U43.22(Y3_N) ; also on sheet 16
DDR3A_CLKP: U43.23(Y3_P) ; also on sheet 16
EMU_TVD: J3.5 R567.1
OSCIN: C24.2 U7.L19(OSCIN) Y2.2
OSCOUT: C23.2 U7.K19(OSCOUT) Y2.1
OSCVSS: C23.1 C24.1 U7.L18(OSCVSS)
PCIE_CLKN: U43.28(Y5_N) ; also on sheet 4
PCIE_CLKP: U43.29(Y5_P) ; also on sheet 4
REFCK_N_C: C339.2 R778.1 U43.9(PRI_REFN)
REFCK_P_C: C338.2 R779.1 U43.8(PRI_REFP)
RTC_XI: C22.2 U7.J19(RTC_XI) Y1.1
RTC_XO: C21.2 U7.H19(RTC_XO) Y1.4
RTCK/GP8[0]: R49.1 U7.K17(RTCK/GP8[0])
SGMII_CLKN: U43.16(Y1_N) ; also on sheet 16
SGMII_CLKP: U43.17(Y1_P) ; also on sheet 16
USB_CLKN: U43.25(Y4_N) ; also on sheet 16
USB_CLKP: U43.26(Y4_P) ; also on sheet 16
XDS_BOOTMODE[0]: U7.U3(VP_DOUT[8]/LCD_D[8]/UPP_XD[0]/GP7[0]/BOOT[0]) ; also on sheet 15
XDS_BOOTMODE[1]: U7.T1(VP_DOUT[9]/LCD_D[9]/UPP_XD[1]/GP7[1]/BOOT[1]) ; also on sheet 15
XDS_BOOTMODE[2]: U7.T2(VP_DOUT[10]/LCD_D[10]/UPP_XD[2]/GP7[2]/BOOT[2]) ; also on sheet 15
XDS_BOOTMODE[3]: U7.T3(VP_DOUT[11]/LCD_D[11]/UPP_XD[3]/GP7[3]/BOOT[3]) ; also on sheet 15
XDS_BOOTMODE[4]: U7.R1(VP_DOUT[12]/LCD_D[12]/UPP_XD[4]/GP7[4]/BOOT[4]) ; also on sheet 15
XDS_BOOTMODE[5]: U7.R2(VP_DOUT[13]/LCD_D[13]/UPP_XD[5]/GP7[5]/BOOT[5]) ; also on sheet 15
XDS_BOOTMODE[6]: U7.R3(VP_DOUT[14]/LCD_D[14]/UPP_XD[6]/GP7[6]/BOOT[6]) ; also on sheet 15
XDS_BOOTMODE[7]: U7.P4(VP_DOUT[15]/LCD_D[15]/UPP_XD[7]/GP7[7]/BOOT[7]) ; also on sheet 15
XDS_SYS_RESETn: R15.1 ; also on sheet 15
XDS_VCC3V3: R50.2 R525.1 R533.2 R543.2 R544.2 R567.2 TP20.1 ; also on sheet 10 15 24 42
N17277378: TP102.1 U43.45(STATUS1/PIN0)
N17277394: R452.1 R463.1 R464.2 U43.6(REF_SEL)
N17277403: C327.2 U43.40(REG_CAP)
N17277433: R416.1 TP89.1
N17277449: R415.1 TP88.1
N17277504: R416.2 U43.32(Y6_P)
N17277515: R415.2 U43.33(Y6_N)
N17277517: C327.1 R757.1
N17278070: R451.1 U43.1(SI_MODE0)
N17278072: R447.1 U43.47(SI_MODE1)
N17278318: C908.1 R777.1 R778.2 R779.2 R780.2
N18154516: C876.1 R763.2
N18162018: C341.2 R446.1 Y5.3
N18162022: C340.2 R445.1 Y5.1
N18202267: TP7.1 U7.T18(CLKOUT/UHPI_HDS2n/GP6[14])
N18202331: R95.2 U7.V2(VP_DOUT[4]/LCD_D[4]/UPP_XD[12]/GP7[12])
N18202517: R544.1 U7.T17(RESETOUTn/UHPI_HASn/GP6[15])
N18202859: R15.2 R520.2 R525.2 U7.K14(RESETn)
N18202879: R533.1 U7.J17(NMIn)
N18202922: R50.1 U7.K16(EMU1)
N18202963: R543.1 U7.J16(EMU0)
N18203030: C404.1 R532.1
N21647391: R438.1 TP100.1
N21647393: R435.1 TP97.1
N21647395: R438.2 U43.14(Y0_P)
N21647404: R435.2 U43.15(Y0_N)
N21672157: R753.1 R754.2 U43.43(PDN)

Not connected (* = marked no-connect by the designer): J3 6* 13* 14* 16* 17* 18* 19* 20*; U7 F1(MMCSD1_DAT[7]/LCD_PCLK/GP8[11]) F2(MMCSD1_DAT[6]/LCD_MCLK/GP8[10]) G1(MMCSD1_DAT[0]/UPP_CHB_CLK/GP8[15]) G2(MMCSD1_CLK/UPP_CHB_START/GP8[14]) G3(UPP_CHB_WAIT/GP8[12]) G4(MMCSD1_DAT[4]/LCD_VSYNC/GP8[8]) H3(VP_CLKIN2/MMCSD1_DAT[3]/GP6[4]) H4(MMCSD1_DAT[5]/LCD_HSYNC/GP8[9]) J3(VP_CLKIN3/MMCSD1_DAT[1]/GP6[2]) J4(MMCSD1_CMD/UPP_CHB_ENABLE/GP8[13]) K3(VP_CLKOUT2/MMCSD1_DAT[2]/GP6[3]) K4(VP_CLKOUT3/GP6[1]) P14(USB1_VDD18)* P15(USB1_VDD33)* P17(VP_DIN[8]/UHPI_HD[0]/UPP_CHA_D[0]/GP6[5]) P18(USB1_DM)* P19(USB1_DP)* R5(LCD_AC_ENB_CSn/GP6[0]) R6(DDR_VREF) R10(DDR_DQM[1]) R11(DDR_DQGATE0) R12(DDR_DQGATE1) R14(VP_DIN[5]/UHPI_HD[13]/UPP_CHA_D[13]/RMII_TXEN) R15(VP_DIN[9]/UHPI_HD[1]/UPP_CHA_D[1]) R16(UHPI_HINTn/GP6[12]) R17(UHPI_HRDYn/GP6[13]) R18(VP_DIN[11]/UHPI_HD[3]/UPP_CHA_D[3]) R19(VP_DIN[10]/UHPI_HD[2]/UPP_CHA_D[2]) T4(DDR_A[11]) T5(DDR_A[13]) T6(DDR_A[9]) T7(DDR_A[1]) T8(DDR_WEn) T9(DDR_BA[1]) T10(DDR_D[10]) T11(DDR_D[9]) T12(DDR_D[11]) T13(DDR_D[8]) T14(DDR_DQS[0]) T15(UHPI_HRWn/UPP_CHA_WAIT/GP6[8]) T16(VP_DIN[12]/UHPI_HD[4]/UPP_CHA_D[4]) U4(DDR_A[8]) U5(DDR_A[4]) U6(DDR_A[7]) U7(DDR_A[0]) U8(DDR_BA[2]) U9(DDR_CASn) U10(DDR_D[12]) U11(DDR_D[14]) U12(DDR_ZP) U13(DDR_D[3]) U14(DDR_D[1]) U15(DDR_D[0]) U16(UHPI_HHWIL/UPP_CHA_ENABLE/GP6[9]) U17(UHPI_HCNTL0/UPP_CHA_CLK/GP6[11]) U18(VP_DIN[7]/UHPI_HD[15]/UPP_CHA_D[15]/RMII_TXD[1]) U19(VP_DIN[13]_FIELD/UHPI_HD[5]/UPP_CHA_D[5]) V1(VP_DOUT[3]/LCD_D[3]/UPP_XD[11]/GP7[11]) V4(DDR_A[12]) V5(DDR_A[5]) V6(DDR_A[3]) V7(DDR_CKE) V8(DDR_BA[0]) V9(DDR_CSn) V10(DDR_D[13]) V11(DDR_DQS[1]) V12(DDR_D[5]) V13(DDR_D[4]) V14(DDR_D[2]) V15(VP_CLKIN1/UHPI_HDS1n/GP6[6]) V16(VP_DIN[6]/UHPI_HD[14]/UPP_CHA_D[14]/RMII_TXD[0]) V17(VP_DIN[3]/UHPI_HD[11]/UPP_CHA_D[11]/RMII_RXD[0]) V18(VP_DIN[15]_VSYNC/UHPI_HD[7]/UPP_CHA_D[7]) V19(VP_DIN[14]_HSYNC/UHPI_HD[6]/UPP_CHA_D[6]) W1(VP_DOUT[0]/LCD_D[0]/UPP_XD8/GPIO7[8]) W2(VP_DOUT[1]/LCD_D[1]/UPP_XD[9]/GP7[9]) W3(VP_DOUT[2]/LCD_D[2]/UPP_XD[10]/GP7[10]) W4(EMB_A[10]) W5(DDR_A[6]) W6(DDR_A[2]) W7(DDR_CLKN) W8(DDR_CLKP) W9(DDR_RASn) W10(DDR_D[15]) W11(DDR_D[7]) W12(DDR_D[6]) W13(DDR_DQM[0]) W14(VP_CLKIN0/UHPI_HCSn/GP6[7]/UPP_2xTXCLK) W15(UHPI_HCNTL1/UPP_CHA_START/GP6[10]) W16(VP_DIN[4]/UHPI_HD[12]/UPP_CHA_D[12]/RMII_RXD[1]) W17(VP_DIN[2]/UHPI_HD[10]/UPP_CHA_D[10]/RMII_RXER) W18(VP_DIN[1]/UHPI_HD[9]/UPP_CHA_D[9]/RMII_MHZ_50_CLK) W19(VP_DIN[0]/UHPI_HD[8]/UPP_CHA_D[8]/RMII_CRS_DV)

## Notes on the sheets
sheet 13
- CDCM62008 Clk2, 100 / 156.25, Power Filter for Clock
- STATUS0 outputs the PLL_LOCK signal
  STATUS1 the LOSS OF REFERENCE.
- 156.25MHz Output
- 156.25MHz Output
- 100MHz Output
- 100MHz Output
- [Note]layout would place R757 and
  C327 close to U43.
- pull-up resister
- Synthesizer mode (high loop bandwidth)
  CDCM6208V1:
  With C1=220pF, R2=400 , C2=22nF and
  Internal components R3=100Ohm, C3=242.5pF,
  fPFD=25MHz, and ICP=2.5mA:
  Loop bandwidth ~ (274kHz)
- Serial Interface Mode or Pin Mode Selection
- MCU_SI_MODE[1:0]
- DESCRIPTION
- 00
- SPI MODE
- (Default)
- 01
- I2C MODE
- 10
- PIN MODE (NO SERIAL PROGRAMMING)
- 11
- RESEERVED
sheet 14
- XDS200 / debug hdr, oscillators
- NOT USED
- NOT USED
- ABM7-24.000MHZ-D2Y-T
- PRODUCTION CARD EDGE
